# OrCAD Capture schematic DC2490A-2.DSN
size Custom; title: MICROPOWER NO-OPTO ISOLATED FLYBACK CONVERTER; rev: 2; note: DEMO CIRCUIT 2490A
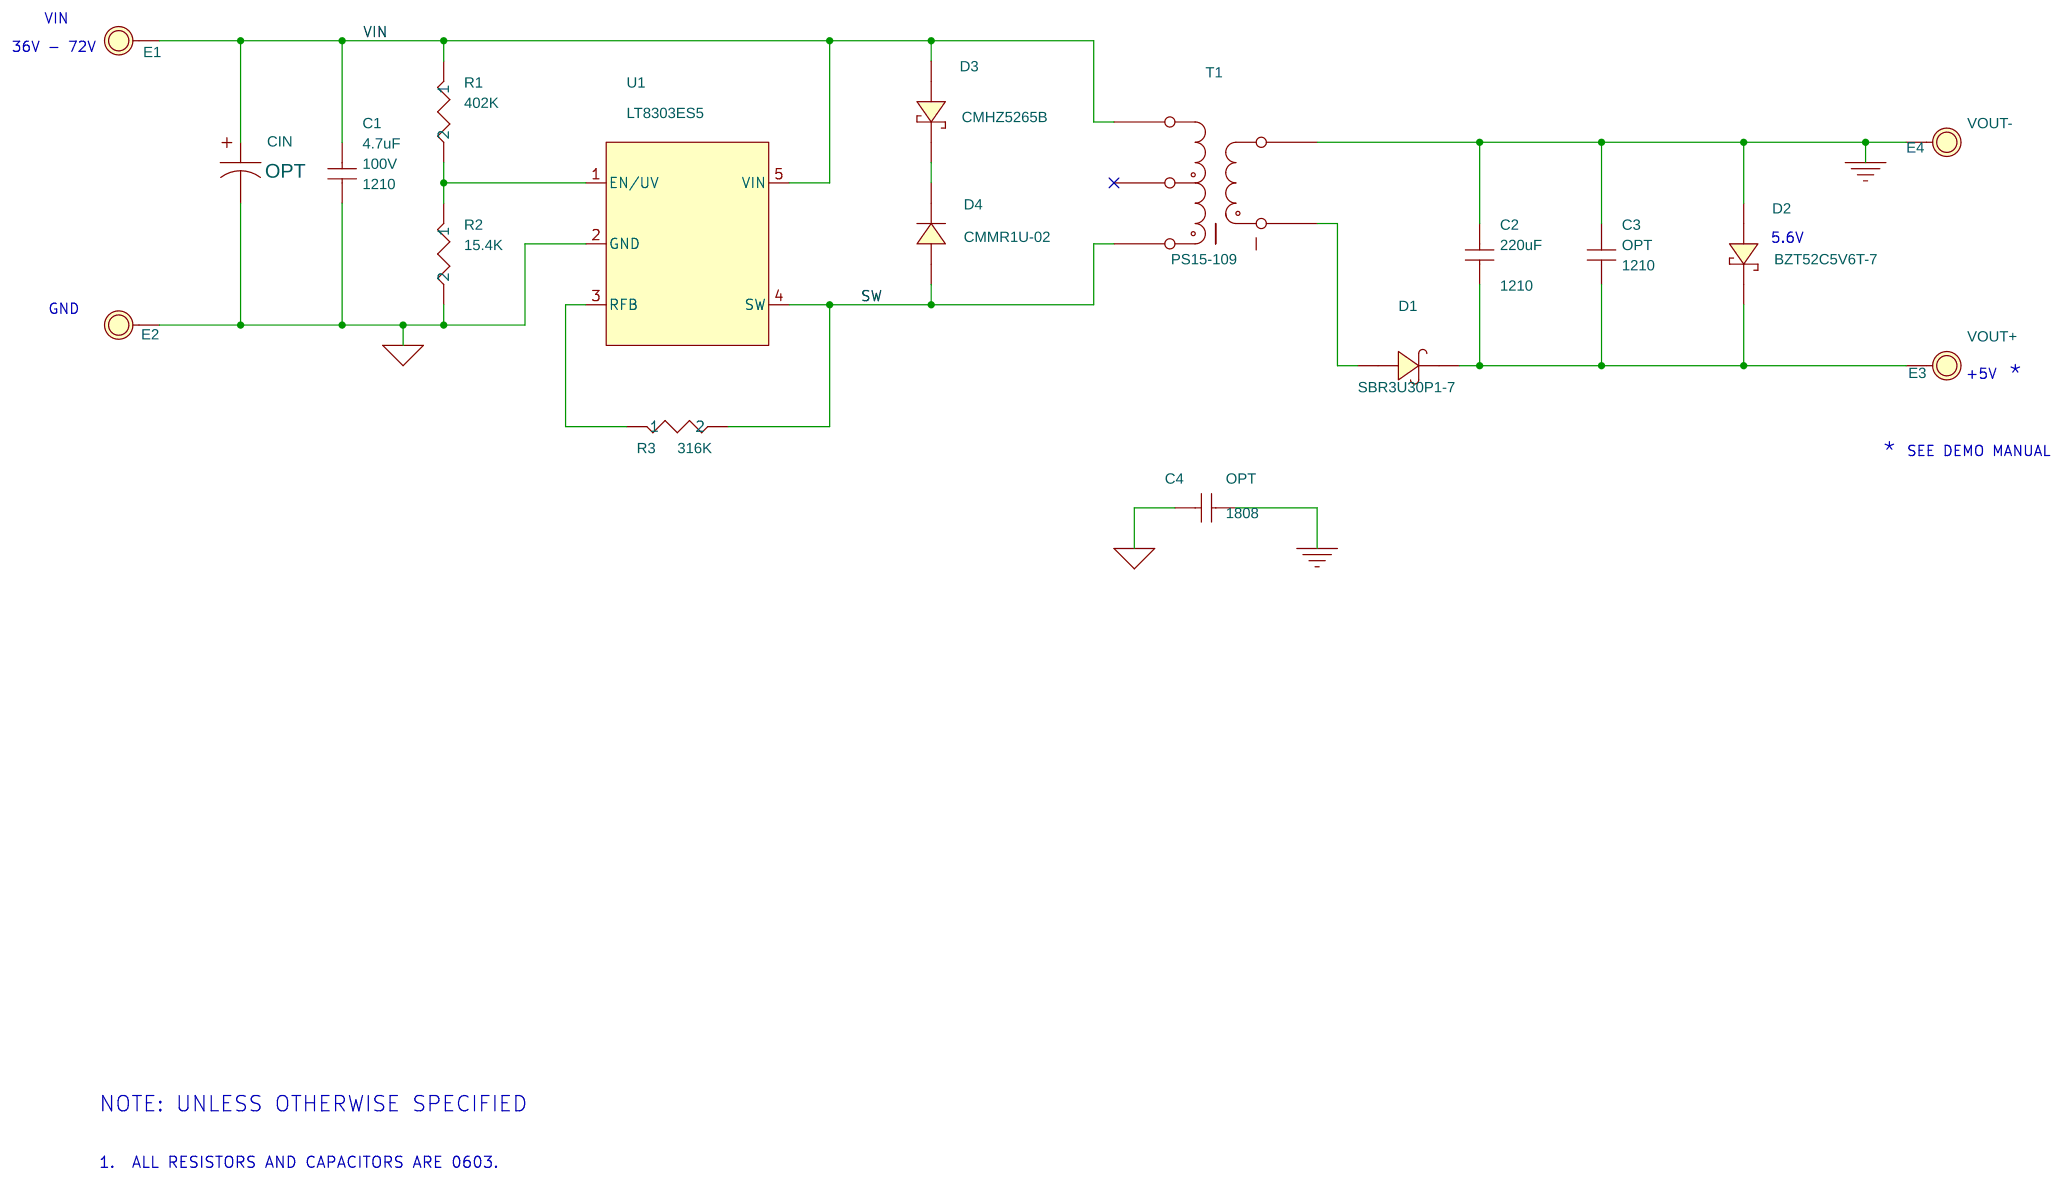
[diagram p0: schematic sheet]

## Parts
C1  4.7uF  [1210]
C2  220uF  [1210]
C3  OPT  [1210]
C4  OPT  [1808]
CIN  OPT  [CAP-CE-BS-6.3X7.7]
D1  SBR3U30P1-7  [POWERDI123]
D2  BZT52C5V6T-7  [SOD-523]
D3  CMHZ5265B  [SOD-123]
D4  CMMR1U-02  [SOD-123]
E1  E_1  [PAD150-095]
E2  E_1  [PAD150-095]
E3  VOUT+  [PAD150-095]
E4  VOUT-  [PAD150-095]
R1  402K  [0603]
R2  15.4K  [0603]
R3  316K  [0603]
T1  PS15-109  [TRAN-PS15-109]
U1  LT8303ES5  [TSOT23-5]

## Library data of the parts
C1 = CAP-NP: CAP, 1210 4.7uF 10% 50V X7R; Part Number: MURATA GRM32ER71H475K; voltage: 100V
C2 C3 = CAP-NP: CAP, 1210 47uF 10% 10V X7R; Part Number: MURATA GRM32ER71A476K; voltage: 6.3V
C4 = CAP-NP: CAP, 1210 4.7uF 10% 50V X7R; Part Number: MURATA GRM32ER71H475K; voltage: 250
CIN = CAP_2: 2nd Part Field: EMZA800ADA100MF80G; COMPFIXED: 10uF,80V; COMPGROUP: NIPPON CHEMI-CON; COMPKEY: 50CE22BS
D1 = DIODE_SCHOTTKY_3: DIODE, SCHOTTKY, BARRIER RECTIFIER 8A; Part Number: MICRO SEMI UPS840
D2 D3 = DIODE_SCHOTTKY_5: DIODE, SCHOTTKY, BARRIER RECTIFIER 8A; Part Number: MICRO SEMI UPS840
D4 = 1N4148W
E1-E4 = E_1: TURRET; Part Number: MILL-MAX 2501-2-00-80-00-00-07-0
R1 = R_2: RES, 0603 357K OHMS 1% 1/16W; Part Number: VISHAY CRCW0603357KFKED; Tol: 1%
R2 = R: RES, 0603 93.1K OHMS 1% 1/16W; Part Number: VISHAY CRCW060393K1FKED; Tol: 1%
R3 = R_1: RES, 0603 84.5K OHMS 1% 1/16W; Part Number: VISHAY CRCW060384K5FKED; Tol: 1%
T1 = 750312251_6: XFMR, 1:1; Part Number: M/A-COM ETC4-1-2 (2-800MHz)
U1 = LT8300: IC, MONOLITHIC FLYBACK CONVERTER; Part Number: LINEAR TECH LT3575EFE

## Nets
GND: C2.2 C3.2 C4.1 D2.2 E4.1(A) T1.1
GNDSIGNAL: C1.1 C4.2 CIN.2 E2.1(A) R2.2 U1.2(GND)
VIN: C1.2 CIN.1 D3.2 E1.1(A) R1.1 T1.6 U1.5(VIN)
SW: D4.2 R3.2 T1.4 U1.4(SW)
N18174947: D1.2 T1.3
N18175113: R3.1 U1.3(RFB)
N18175150: C2.1 C3.1 D1.1 D2.1 E3.1(A)
N18234973: R1.2 R2.1 U1.1(EN/UV)
N18249142: D3.1 D4.1

Not connected (* = marked no-connect by the designer): T1 5*

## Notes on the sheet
- VIN
- 36V - 72V
- 5.6V
- GND
- +5V
- *
- *
- SEE DEMO MANUAL
- NOTE: UNLESS OTHERWISE SPECIFIED
- 1.  ALL RESISTORS AND CAPACITORS ARE 0603.
